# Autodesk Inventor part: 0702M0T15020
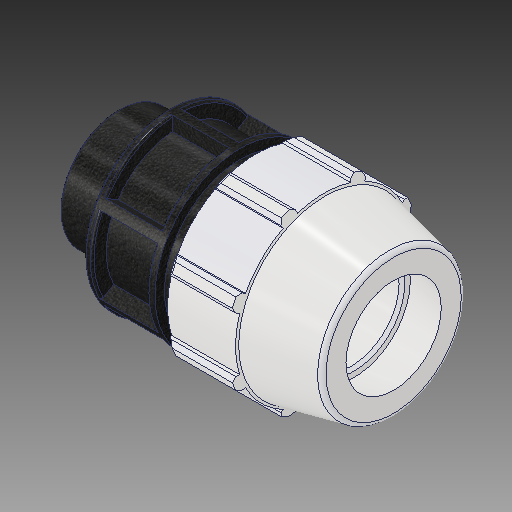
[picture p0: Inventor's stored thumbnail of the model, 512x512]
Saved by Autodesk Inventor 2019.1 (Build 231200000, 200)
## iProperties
Created: 2017-02
Part Number: 0702M0T15020
Material: PVC-Piping
Description: PLASSON MALE ADAPTOR 1 1/2'' - 2''M
Document SubType Name: Modeling
Designer: KIM
Mass: 92.6774 g
Surface Area: 199.44 cm^2
Volume: 66.1981 cm^3
Density: 1.4 g/cm^3
Appearance: PTFE
Author: KIM
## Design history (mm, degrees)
derived "0702M0T.ipt"
feature "Solid1::0702M0T.ipt"
tag "TaggingFeature1"
body "Solid1"
other parameters: "d2" = 48.1, "d4" = 19.84829, "d5" = 34.7345, "d7" = 96.012, "d8" = 72.009, "d9" = 19.84829, "d11" = 3.96966, "d12" = 76.8096, "d13" = 120 deg, "d14" = 72.15, "d15" = 12 deg, "d16" = 86.4108, "d18" = 2.405, "d19" = 35 deg, "d20" = 17.5 deg, "d21" = 89.29116, "d23" = 0, "d25" = 360 deg, "d27" = 1.92024, "d34" = 4.8006, "d36" = 0, "d42" = 34.7345, "d43" = 2.88036, "d46" = 1.443, "d51" = 138.938, "d52" = 25.908, "d53" = 0.962, "d55" = 360 deg, "d57" = 59.614, "d58" = 41.7298, "d59" = 27.7876, "d61" = 30.988, "d_" = 48.1, "E_" = 96.012, "H_" = 138.938, "l_" = 106.934, "l_2" = 25.908, "G_" = 59.614
